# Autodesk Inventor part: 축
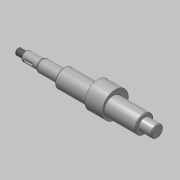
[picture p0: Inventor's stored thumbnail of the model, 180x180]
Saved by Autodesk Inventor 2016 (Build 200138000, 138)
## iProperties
Created: 2015-12
Part Number: 축
Document SubType Name: Modeling
Designer: mdu
Density: 7.86 g/cm^3
Material: 강철, 연강
Appearance: 강철
Mass: 489.928 g
Surface Area: 127.026 cm^2
Volume: 62.3318 cm^3
Author: mdu
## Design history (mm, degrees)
sketch "스케치1"
  geometry: L1 (62, 100.9)-(62, 67.1) reference; L2 (51, 101.2)-(51, 84) reference; L3 (-51, 84)-(-51, 101.2) reference; L4 (-62, 67.1)-(-62, 100.9) reference; L5 (-51.6, 91.5)-(-61.4, 91.5) reference; L6 (51.6, 91.5)-(61.4, 91.5) reference; L7 (67, 84)-(-109, 84); L8 (-77, 64.201)-(-77, 103.799) reference; L9 (67, 84)-(67, 91.5); L10 (67, 91.5)-(51, 91.5); L11 (51, 91.5)-(51, 95.5); L12 (51, 95.5)-(-51, 95.5); L13 (-51, 95.5)-(-51, 91.5); L14 (-51, 91.5)-(-79, 91.5); L15 (-79, 91.5)-(-79, 90); L16 (-79, 90)-(-99, 90); L17 (-99, 90)-(-99, 88); L18 (-99, 88)-(-109, 88); L19 (-109, 88)-(-109, 84); 2 further points
  constraints: 28 end point, 7 parallel, 5 point on line, 4 perpendicular, 2 collinear, 2 horizontal, 1 midpoint, 4 other
  dimensions: "d0" = 5 distance from line of L7.start L1; "d2" = 2 distance between parallel lines of L15 L8; "d3" = 23 diameter of L12 L7; "d4" = 12 diameter of L16 L7; "d7" = 20 distance of L15.end L16.end; "d8" = 10 distance between parallel lines of L17 L19; "d9" = 8 diameter of L18 L7
revolve "회전1" sketch "스케치1" stored, may be unused: angle "d10" = 90 deg
sketch "스케치2"
  geometry: C1 r 11.5 at (84, 0) reference; C2 r 11.5 at (84, 0) reference; C3 r 16.5 at (87, 0); 1 further point
  constraints: 1 centre point, 1 horizontal alignment
  dimensions: "d11" = 33 diameter of C3; "d12" = 3 distance of C3.centre C1.centre
extrude "돌출1" join sketch "스케치2" stored distance "d13" = 22; taper "d14" = 0 deg
chamfer "모따기1" distance "d15" = 1; stored, may be unused: second distance "d16" = 2, angle "d17" = 45 deg
feature "스레드1" dims "d18" = 8, "d19" = 0
node "작업 평면1"
sketch "스케치3"
  geometry: L1 (-5, -2)-(3, -2); L2 (3, 2)-(-5, 2); L3 (-10, -5)-(-10, 5) reference; A1 r 2 centre (3, 0) between (3, -2) and (3, 2); A2 r 2 centre (-5, 0) between (-5, 2) and (-5, -2); 2 further points
  constraints: 4 end point, 4 point on circle, 4 tangent, 2 centre point, 1 horizontal, 1 horizontal alignment, 1 midpoint, 1 parallel
  dimensions: "d20" = 4 distance between parallel lines of L1 L2; "d21" = 12 dimension on A1 A2; "d22" = 3 distance edge to line of A2 L3
extrude "돌출2" cut sketch "스케치3" distance "d23" = 2.5; taper "d24" = 0 deg
fillet "모깎기1" dims "d25" = 0.3
chamfer "모따기2" distance "d27" = 1.65; stored, may be unused: second distance "d28" = 2, angle "d29" = 30 deg
fillet "모깎기3" dims "d30" = 2
node "솔리드1"
node "참조1"
node "참조2"
node "참조3"
node "참조4"
node "참조5"
node "투영된 루프1"
